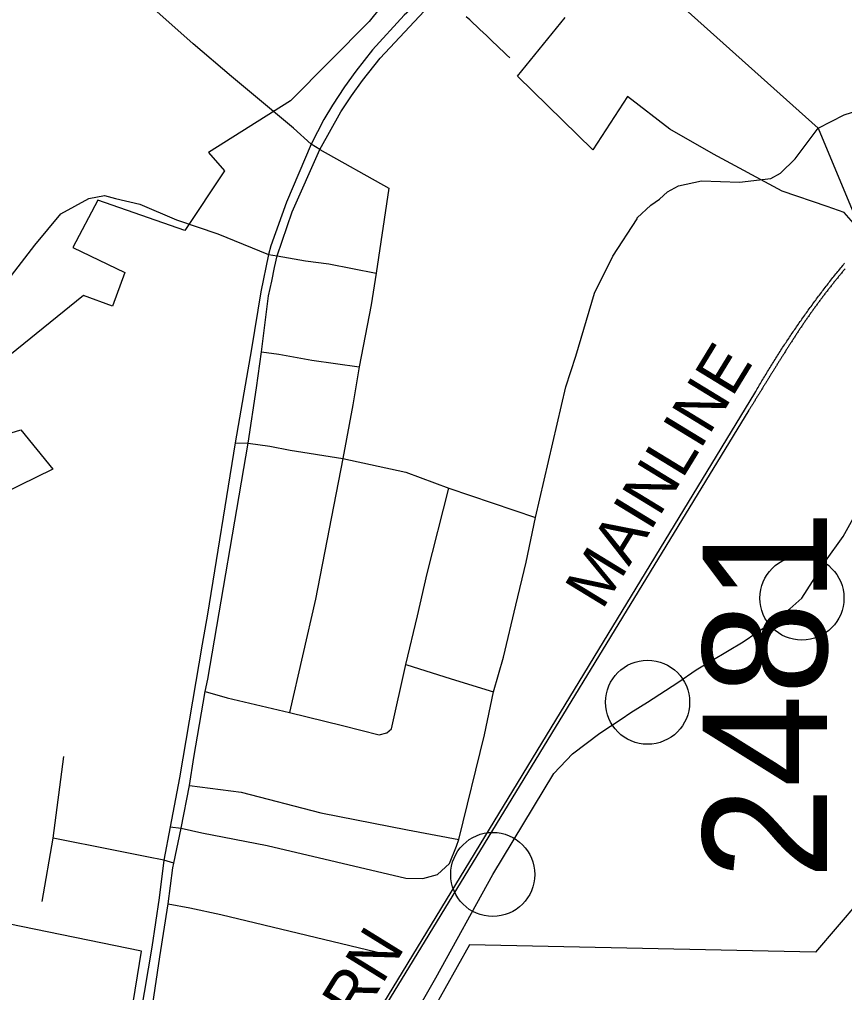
# Model space of a CAD drawing. Extents: x 1372027 to 1374286, y 553832 to 556743.
# Drawn here: x 1373241.2 to 1373303, y 554244.7 to 554317.6 of the extents above; entities that cross this region are included whole.
import ezdxf

# ---------------------------------------------------------------- set-up
doc = ezdxf.new("R2010")
doc.units = 0
for name, color, linetype in [('Old_Level_12', 7, 'Continuous'), ('Old_Level_44', 7, 'Continuous'), ('Prop DGN Element Guardrail', 7, 'Continuous'), ('Prop Dimension Text', 7, 'Continuous'), ('Prop Paved Shoulder', 7, 'Continuous'), ('Sheet Clip Boundary CELL', 7, 'Continuous'), ('Sheet Data Field CELL', 7, 'Continuous'), ('Sheet Sticker Preliminary CELL', 7, 'Continuous')]:
    doc.layers.add(name, color=color, linetype=linetype)

msp = doc.modelspace()

# ---------------------------------------------------------------- linework, layer by layer
at = {"layer": 'Old_Level_44'}
for points in [[(1373296.272, 554289.58), (1373296.331, 554289.684), (1373296.389, 554289.783), (1373296.448, 554289.884), (1373296.508, 554289.987), (1373296.566, 554290.086), (1373296.625, 554290.19), (1373296.684, 554290.291), (1373296.743, 554290.392), (1373296.803, 554290.493), (1373296.863, 554290.594), (1373296.923, 554290.693), (1373296.983, 554290.797), (1373297.044, 554290.896), (1373297.104, 554290.995), (1373297.164, 554291.098), (1373297.225, 554291.197), (1373297.287, 554291.296), (1373297.347, 554291.397), (1373297.409, 554291.496), (1373297.47, 554291.596), (1373297.533, 554291.697), (1373297.594, 554291.796), (1373297.655, 554291.895), (1373297.719, 554291.996), (1373297.78, 554292.095), (1373297.844, 554292.194), (1373297.905, 554292.295), (1373297.969, 554292.392), (1373298.031, 554292.491), (1373298.096, 554292.59), (1373298.158, 554292.689), (1373298.221, 554292.788), (1373298.286, 554292.885), (1373298.349, 554292.984), (1373298.413, 554293.081), (1373298.478, 554293.182), (1373298.541, 554293.279), (1373298.606, 554293.376), (1373298.671, 554293.475), (1373298.736, 554293.572), (1373298.802, 554293.671), (1373298.865, 554293.768), (1373298.931, 554293.865), (1373298.997, 554293.962), (1373299.062, 554294.061), (1373299.128, 554294.155), (1373299.196, 554294.252), (1373299.26, 554294.349), (1373299.326, 554294.446), (1373299.394, 554294.545), (1373299.461, 554294.642), (1373299.527, 554294.737), (1373299.594, 554294.834), (1373299.661, 554294.931), (1373299.729, 554295.025), (1373299.796, 554295.122), (1373299.863, 554295.217), (1373299.931, 554295.314), (1373300, 554295.409), (1373300.068, 554295.505), (1373300.137, 554295.6), (1373300.204, 554295.695), (1373300.272, 554295.792), (1373300.342, 554295.887), (1373300.41, 554295.979), (1373300.48, 554296.074), (1373300.55, 554296.169), (1373300.619, 554296.263), (1373300.689, 554296.358), (1373300.759, 554296.453), (1373300.828, 554296.548), (1373300.898, 554296.642), (1373300.969, 554296.737), (1373301.039, 554296.827), (1373301.109, 554296.922), (1373301.18, 554297.017), (1373301.251, 554297.109), (1373301.322, 554297.204), (1373301.394, 554297.295), (1373301.465, 554297.389), (1373301.535, 554297.482), (1373301.607, 554297.577), (1373301.679, 554297.667), (1373301.753, 554297.76), (1373301.822, 554297.854), (1373301.897, 554297.947), (1373301.969, 554298.037), (1373302.041, 554298.13), (1373302.114, 554298.223), (1373302.186, 554298.313), (1373302.26, 554298.406), (1373302.334, 554298.498), (1373302.406, 554298.589), (1373302.479, 554298.681), (1373302.553, 554298.769), (1373302.628, 554298.862), (1373302.701, 554298.955), (1373302.775, 554299.043), (1373302.849, 554299.135)], [(1373303.028, 554298.892), (1373302.984, 554298.838), (1373302.94, 554298.787), (1373302.895, 554298.731), (1373302.851, 554298.679), (1373302.806, 554298.625), (1373302.762, 554298.571), (1373302.718, 554298.518), (1373302.675, 554298.466), (1373302.63, 554298.41), (1373302.587, 554298.358), (1373302.542, 554298.302), (1373302.499, 554298.251), (1373302.455, 554298.195), (1373302.412, 554298.143), (1373302.369, 554298.087), (1373302.324, 554298.035), (1373302.281, 554297.979), (1373302.238, 554297.928), (1373302.196, 554297.874), (1373302.152, 554297.82), (1373302.109, 554297.766), (1373302.066, 554297.71), (1373302.023, 554297.654), (1373301.981, 554297.602), (1373301.937, 554297.547), (1373301.895, 554297.493), (1373301.852, 554297.437), (1373301.81, 554297.385), (1373301.766, 554297.329), (1373301.725, 554297.275), (1373301.683, 554297.219), (1373301.641, 554297.163), (1373301.597, 554297.109), (1373301.555, 554297.053), (1373301.514, 554297), (1373301.472, 554296.944), (1373301.43, 554296.888), (1373301.389, 554296.834), (1373301.347, 554296.778), (1373301.305, 554296.724), (1373301.263, 554296.668), (1373301.222, 554296.612), (1373301.18, 554296.558), (1373301.139, 554296.502), (1373301.097, 554296.446), (1373301.056, 554296.39), (1373301.014, 554296.334), (1373300.974, 554296.278), (1373300.933, 554296.225), (1373300.892, 554296.169), (1373300.85, 554296.11), (1373300.809, 554296.057), (1373300.769, 554296.001), (1373300.729, 554295.943), (1373300.688, 554295.889), (1373300.648, 554295.831), (1373300.607, 554295.775), (1373300.567, 554295.721), (1373300.526, 554295.663), (1373300.486, 554295.607), (1373300.446, 554295.551), (1373300.407, 554295.495), (1373300.366, 554295.437), (1373300.326, 554295.378), (1373300.287, 554295.325), (1373300.246, 554295.266), (1373300.208, 554295.21), (1373300.168, 554295.152), (1373300.128, 554295.096), (1373300.089, 554295.04), (1373300.049, 554294.982), (1373300.011, 554294.924), (1373299.971, 554294.87), (1373299.931, 554294.812), (1373299.892, 554294.754), (1373299.855, 554294.696), (1373299.815, 554294.638), (1373299.777, 554294.584), (1373299.737, 554294.526), (1373299.7, 554294.468), (1373299.66, 554294.41), (1373299.622, 554294.354), (1373299.583, 554294.295), (1373299.545, 554294.237), (1373299.506, 554294.179), (1373299.468, 554294.121), (1373299.43, 554294.063), (1373299.392, 554294.007), (1373299.354, 554293.949), (1373299.316, 554293.891), (1373299.278, 554293.833), (1373299.241, 554293.774), (1373299.203, 554293.718), (1373299.165, 554293.656), (1373299.128, 554293.6), (1373299.09, 554293.542), (1373299.054, 554293.484), (1373299.015, 554293.426), (1373298.978, 554293.365)], [(1373302.849, 554299.135), (1373302.879, 554299.172), (1373302.909, 554299.209), (1373302.937, 554299.243), (1373302.966, 554299.28), (1373302.995, 554299.316)], [(1373298.978, 554293.365), (1373298.946, 554293.316), (1373298.915, 554293.264), (1373298.881, 554293.212), (1373298.849, 554293.161), (1373298.817, 554293.111), (1373298.785, 554293.062), (1373298.753, 554293.008), (1373298.72, 554292.958), (1373298.689, 554292.907), (1373298.655, 554292.857), (1373298.623, 554292.803), (1373298.592, 554292.754), (1373298.558, 554292.702), (1373298.527, 554292.653), (1373298.494, 554292.599), (1373298.463, 554292.549), (1373298.43, 554292.498), (1373298.398, 554292.446), (1373298.366, 554292.394), (1373298.335, 554292.345), (1373298.301, 554292.291), (1373298.27, 554292.241), (1373298.237, 554292.19), (1373298.205, 554292.14), (1373298.173, 554292.086), (1373298.141, 554292.037), (1373298.108, 554291.985), (1373298.077, 554291.936), (1373298.044, 554291.882), (1373298.013, 554291.832), (1373297.98, 554291.781), (1373297.948, 554291.731), (1373297.917, 554291.677), (1373297.885, 554291.628), (1373297.852, 554291.576), (1373297.82, 554291.524), (1373297.789, 554291.473), (1373297.756, 554291.423), (1373297.724, 554291.372), (1373297.693, 554291.318), (1373297.661, 554291.268), (1373297.628, 554291.217), (1373297.597, 554291.165), (1373297.565, 554291.113), (1373297.533, 554291.064), (1373297.501, 554291.012), (1373297.469, 554290.96), (1373297.437, 554290.909), (1373297.405, 554290.859), (1373297.373, 554290.805), (1373297.341, 554290.754), (1373297.31, 554290.704), (1373297.277, 554290.65), (1373297.246, 554290.601), (1373297.214, 554290.549), (1373297.182, 554290.5), (1373297.15, 554290.446), (1373297.119, 554290.394), (1373297.086, 554290.345), (1373297.055, 554290.291), (1373297.023, 554290.241), (1373296.991, 554290.19), (1373296.959, 554290.138), (1373296.928, 554290.086), (1373296.895, 554290.035), (1373296.864, 554289.985), (1373296.833, 554289.931), (1373296.802, 554289.88), (1373296.768, 554289.83), (1373296.737, 554289.776), (1373296.706, 554289.727), (1373296.673, 554289.675), (1373296.642, 554289.623), (1373296.611, 554289.572), (1373296.58, 554289.52), (1373296.546, 554289.47), (1373296.515, 554289.417), (1373296.484, 554289.365), (1373296.452, 554289.315), (1373296.42, 554289.264), (1373296.389, 554289.212), (1373296.358, 554289.16), (1373296.326, 554289.109), (1373296.295, 554289.057), (1373296.263, 554289.005), (1373296.232, 554288.954), (1373296.2, 554288.902), (1373296.169, 554288.85), (1373296.137, 554288.799), (1373296.106, 554288.749), (1373296.073, 554288.695), (1373296.042, 554288.644), (1373296.01, 554288.594), (1373295.978, 554288.54), (1373295.948, 554288.491), (1373295.917, 554288.439), (1373295.885, 554288.385), (1373295.853, 554288.336), (1373295.822, 554288.284)], [(1373259.14, 554228.722), (1373266.657, 554240.88), (1373276.391, 554256.901), (1373296.272, 554289.58)], [(1373295.822, 554288.284), (1373270.668, 554247.079), (1373259.467, 554228.731)]]:
    msp.add_lwpolyline(points, dxfattribs=at)
at = {"layer": 'Prop DGN Element Guardrail'}
for p, q in [((1373253.29, 554256.962), (1373253.909, 554260.178)), ((1373252.469, 554257.073), (1373251.986, 554254.562)), ((1373252.746, 554254.351), (1373253.29, 554256.962))]:
    msp.add_line(p, q, dxfattribs=at)
for points in [[(1373280.754, 554327.256), (1373278.245, 554324.938), (1373275.693, 554322.923), (1373273.791, 554321.244), (1373270.007, 554317.898), (1373267.63, 554315.301), (1373266.362, 554313.685), (1373265.531, 554312.513), (1373264.638, 554311.157), (1373263.972, 554310.079), (1373263.033, 554308.223)], [(1373263.668, 554307.836), (1373265.252, 554310.65), (1373266.038, 554311.847), (1373266.869, 554312.988), (1373268.2, 554314.667), (1373271.497, 554318.184), (1373274.077, 554320.262), (1373279.75, 554325.173), (1373279.845, 554325.299), (1373281.274, 554326.653)], [(1373263.033, 554308.223), (1373261.189, 554303.876), (1373260.016, 554300.613), (1373259.826, 554299.948)], [(1373260.474, 554299.856), (1373261.607, 554303.147), (1373263.668, 554307.836)], [(1373259.826, 554299.948), (1373259.255, 554297.16), (1373258.558, 554292.878), (1373258.078, 554290.164), (1373257.344, 554285.854)], [(1373259.303, 554292.672), (1373259.837, 554296.86), (1373260.093, 554297.967), (1373260.282, 554298.974), (1373260.474, 554299.856)], [(1373258.313, 554285.83), (1373258.942, 554289.978), (1373259.303, 554292.672)], [(1373257.344, 554285.854), (1373255.26, 554273.016), (1373254.866, 554270.754), (1373253.16, 554260.737), (1373252.469, 554257.073)], [(1373255.093, 554267.204), (1373255.275, 554268.129), (1373258.313, 554285.83)], [(1373253.909, 554260.178), (1373254.226, 554262.278), (1373255.093, 554267.204)], [(1373251.986, 554254.562), (1373251.629, 554251.748), (1373251.09, 554248.048), (1373249.081, 554236.251), (1373246.728, 554222.84)], [(1373252.317, 554251.293), (1373252.671, 554253.991), (1373252.746, 554254.351)], [(1373247.726, 554223.085), (1373250.014, 554236.09), (1373251.69, 554247.34), (1373252.317, 554251.293)]]:
    msp.add_lwpolyline(points, dxfattribs=at)
at = {"layer": 'Prop Dimension Text'}
msp.add_line((1373245.898, 554220.533), (1373250.32, 554247.745), dxfattribs=at)
for points in [[(1373284.801, 554333.322), (1373283.254, 554331.221), (1373281.567, 554329.337), (1373278.755, 554326.801), (1373273.58, 554322.761), (1373275.169, 554326.459), (1373273.955, 554326.851), (1373272.776, 554324.858), (1373270.564, 554321.415), (1373267.369, 554317.408), (1373261.489, 554311.479)], [(1373316.893, 554269.383), (1373314.34, 554273.093), (1373312.947, 554278.889), (1373310.859, 554287.699), (1373308.77, 554293.727), (1373307.725, 554296.277), (1373306.333, 554299.407), (1373303.663, 554302.305), (1373302.967, 554303.116), (1373301.695, 554303.56), (1373298.304, 554304.708), (1373293.176, 554307.47), (1373289.907, 554309.348), (1373286.72, 554311.81), (1373284.124, 554307.798), (1373278.481, 554313.317), (1373282.051, 554317.716)], [(1373261.489, 554311.479), (1373255.348, 554307.59), (1373256.533, 554306.236), (1373253.569, 554301.752), (1373247.046, 554304.036), (1373245.183, 554300.483), (1373249.079, 554298.621), (1373248.139, 554296.08), (1373245.96, 554296.877), (1373230.953, 554284.745), (1373230.969, 554283.645)], [(1373250.32, 554247.745), (1373215.338, 554254.913), (1373213.16, 554251.073), (1373203.267, 554261.672), (1373193.673, 554271.203), (1373185.76, 554278.678), (1373175.381, 554288.728), (1373165.492, 554298.26), (1373159.341, 554303.68), (1373151.666, 554295.461)], [(1373230.969, 554283.645), (1373241.276, 554286.816), (1373243.681, 554283.88), (1373231.269, 554277.806), (1373233.097, 554274.567), (1373224.726, 554276.693), (1373225.536, 554280.635)], [(1373348.589, 554205.688), (1373344.519, 554207.628), (1373339.27, 554210.775), (1373337.07, 554211.815), (1373338.314, 554218.698), (1373339.658, 554218.467), (1373339.77, 554221.007), (1373341.001, 554225.278), (1373327.007, 554226.663), (1373323.872, 554229.318), (1373318.274, 554235.897), (1373312.453, 554241.206), (1373306.855, 554246.978), (1373304.056, 554251.479), (1373300.809, 554247.67), (1373274.885, 554248.238), (1373271.198, 554241.626), (1373266.228, 554233.279), (1373267.992, 554232.205), (1373269.845, 554229.371)]]:
    msp.add_lwpolyline(points, dxfattribs=at)
at = {"layer": 'Prop Paved Shoulder'}
for p, q in [((1373263.668, 554307.836), (1373263.033, 554308.223)), ((1373259.826, 554299.948), (1373260.474, 554299.856)), ((1373257.344, 554285.854), (1373258.313, 554285.83)), ((1373273.342, 554282.461), (1373279.837, 554280.254)), ((1373243.703, 554256.228), (1373244.486, 554262.346)), ((1373252.469, 554257.073), (1373253.29, 554256.962)), ((1373242.877, 554251.47), (1373243.703, 554256.228)), ((1373252.746, 554254.351), (1373251.986, 554254.562))]:
    msp.add_line(p, q, dxfattribs=at)
for points in [[(1373301.014, 554309.425), (1373302.952, 554310.421), (1373305.844, 554311.344), (1373311.125, 554312.813), (1373315.619, 554314.22), (1373318.881, 554315.279), (1373321.821, 554316.251), (1373326.2, 554317.745), (1373336.912, 554321.186), (1373340.336, 554322.203), (1373344.715, 554323.65), (1373346.781, 554324.285), (1373349.424, 554325.985), (1373350.401, 554326.824), (1373351.506, 554327.687), (1373353.635, 554330.214), (1373356.836, 554334.171), (1373362.701, 554340.741), (1373366.326, 554344.792), (1373371.54, 554350.942), (1373373.78, 554353.503)], [(1373263.033, 554308.223), (1373261.712, 554309.427), (1373257.052, 554313.298), (1373254.188, 554315.751), (1373248.327, 554320.997), (1373246.315, 554322.451), (1373245.635, 554322.942), (1373244.215, 554323.918), (1373243.55, 554324.425), (1373243.201, 554325.09), (1373243.518, 554326.579), (1373244.197, 554328.126)], [(1373281.274, 554326.653), (1373282.798, 554325.352), (1373285.113, 554323.611), (1373286.326, 554322.487), (1373287.517, 554321.495), (1373287.957, 554321.12), (1373289.068, 554320.194), (1373290.101, 554319.227), (1373301.014, 554309.425)], [(1373279.837, 554280.254), (1373282.097, 554290.041), (1373282.858, 554292.337), (1373284.259, 554297.053), (1373285.622, 554299.841), (1373287.443, 554302.62), (1373287.439, 554302.706), (1373288.481, 554303.646), (1373289.116, 554304.097), (1373289.732, 554304.658), (1373290.559, 554305.098), (1373292.268, 554305.484), (1373295.123, 554305.391), (1373297.468, 554305.66), (1373298.184, 554306.063), (1373299.291, 554307.137), (1373301.014, 554309.425)], [(1373301.014, 554309.425), (1373303.562, 554303.303), (1373304.672, 554301.119)], [(1373263.668, 554307.836), (1373268.834, 554304.927), (1373267.903, 554298.572)], [(1373240.326, 554298.051), (1373242.316, 554300.658), (1373244.279, 554302.995), (1373246.379, 554304.162), (1373247.537, 554304.382), (1373248.363, 554304.162), (1373250.183, 554303.721), (1373252.939, 554302.564), (1373256.026, 554301.517), (1373259.826, 554299.948)], [(1373260.474, 554299.856), (1373262.615, 554299.472), (1373264.359, 554299.251), (1373267.903, 554298.572)], [(1373267.903, 554298.572), (1373267.518, 554296.184), (1373266.617, 554291.552)], [(1373259.303, 554292.672), (1373260.614, 554292.485), (1373263.073, 554292.043), (1373266.617, 554291.552)], [(1373266.617, 554291.552), (1373266.144, 554288.69), (1373265.388, 554284.684)], [(1373269.635, 554240.975), (1373272.362, 554245.746), (1373276.633, 554253.502), (1373281.203, 554261.065), (1373282.61, 554262.552), (1373284.65, 554264.094), (1373286.249, 554265.141), (1373286.965, 554265.637), (1373288.233, 554266.409), (1373290.494, 554267.896), (1373291.872, 554268.833), (1373295.397, 554270.939), (1373297.433, 554272.324), (1373298.899, 554273.415), (1373299.795, 554274.213), (1373301.551, 554276.984), (1373302.893, 554278.828), (1373304.011, 554280.84), (1373305.577, 554283.366), (1373306.937, 554285.327), (1373308.104, 554286.471), (1373309.082, 554287.101), (1373310.548, 554287.878), (1373311.362, 554288.486)], [(1373258.313, 554285.83), (1373259.932, 554285.599), (1373261.456, 554285.304), (1373265.388, 554284.684)], [(1373265.388, 554284.684), (1373263.363, 554274.123), (1373261.415, 554265.65)], [(1373265.388, 554284.684), (1373270.118, 554283.647), (1373273.342, 554282.461)], [(1373270.124, 554269.225), (1373270.986, 554272.873), (1373271.722, 554276.051), (1373273.342, 554282.461)], [(1373276.688, 554267.195), (1373277.433, 554269.775), (1373278.356, 554273.686), (1373279.135, 554276.906), (1373279.837, 554280.254)], [(1373261.415, 554265.65), (1373265.374, 554264.676), (1373268.126, 554263.956), (1373268.692, 554264.109), (1373269.043, 554264.428), (1373270.124, 554269.225)], [(1373270.124, 554269.225), (1373273.509, 554268.153), (1373276.688, 554267.195)], [(1373255.093, 554267.204), (1373256.743, 554266.735), (1373261.415, 554265.65)], [(1373274.102, 554256.123), (1373276.007, 554263.975), (1373276.688, 554267.195)], [(1373253.909, 554260.178), (1373257.776, 554259.68), (1373263.752, 554258.113), (1373270.241, 554256.842), (1373274.102, 554256.123)], [(1373253.29, 554256.962), (1373254.832, 554256.626), (1373259.735, 554255.664), (1373270.118, 554253.223), (1373271.406, 554253.189), (1373272.485, 554253.502), (1373273.389, 554254.336), (1373273.904, 554255.627), (1373274.102, 554256.123)], [(1373251.986, 554254.562), (1373250.708, 554254.813), (1373248.223, 554255.321), (1373243.703, 554256.228)], [(1373252.317, 554251.293), (1373253.926, 554250.993), (1373256.271, 554250.502), (1373269.144, 554247.416)]]:
    msp.add_lwpolyline(points, dxfattribs=at)
at = {"layer": 'Sheet Clip Boundary CELL'}
for centre in [(1373299.795, 554274.213), (1373288.233, 554266.409), (1373276.633, 554253.502)]:
    msp.add_circle(centre, 3.15, dxfattribs=at)
at = {"layer": 'Sheet Data Field CELL'}
msp.add_line((1373292.409, 554282.469), (1373292.409, 554282.469), dxfattribs=at)
at = {"layer": 'Sheet Sticker Preliminary CELL'}
msp.add_lwpolyline([(1373277.909, 554314.687), (1373277.658, 554314.924), (1373277.409, 554315.163), (1373277.16, 554315.402), (1373276.912, 554315.641), (1373276.663, 554315.88), (1373276.414, 554316.119), (1373276.166, 554316.358), (1373275.916, 554316.595), (1373275.665, 554316.831), (1373275.413, 554317.066), (1373275.16, 554317.301), (1373274.905, 554317.531), (1373274.648, 554317.759)], dxfattribs=at)

# ---------------------------------------------------------------- texts
at = {"layer": 'Old_Level_12'}
msp.add_text('2481', height=9.3012, rotation=90, dxfattribs=at).set_placement((1373301.669, 554253.138))
at = {"layer": 'Sheet Data Field CELL'}
for s, rotation, p in [('MAINLINE', 58.59757, (1373284.832, 554273.257)), ('SOUTHERN', 58.27551, (1373256.5, 554226.045))]:
    msp.add_text(s, height=3.4449, rotation=rotation, dxfattribs=at).set_placement(p)

doc.saveas('drawing.dxf')
